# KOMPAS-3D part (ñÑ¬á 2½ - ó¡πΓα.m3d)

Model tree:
1. Эскиз:1
2. Операция выдавливания:1
     Расстояние 1 = 0.6
3. Эскиз:2
4. Вырезать элемент выдавливания:1
     Толщина стенки 1 = 3; Толщина стенки 2 = 3; Расстояние 1 = 10
5. Эскиз:3
6. Вырезать элемент выдавливания:2
     Толщина стенки 1 = 3; Толщина стенки 2 = 3; Расстояние 1 = 10
7. Эскиз:4
8. Вырезать элемент выдавливания:3
     Толщина стенки 1 = 3; Толщина стенки 2 = 3; Расстояние 1 = 10
9. Эскиз:5
10. Вырезать элемент выдавливания:4
     Толщина стенки 1 = 3; Толщина стенки 2 = 3; Расстояние 1 = 10
